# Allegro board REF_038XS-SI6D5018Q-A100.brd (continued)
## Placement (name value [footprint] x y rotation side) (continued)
NOREF#498  -  []  266.97 246.58 0 top
NOREF#499  -  []  236.65 207.92 0 top
NOREF#500  -  []  232.14 182.07 0 top
NOREF#501  -  []  102.38 170.43 0 top
NOREF#502  -  []  227.91 178.48 90 top
NOREF#503  -  []  232.16 241.38 0 top
NOREF#504  -  []  211.64 253.86 90 top
NOREF#505  -  []  252.33 242.3 90 top
NOREF#506  -  []  269.23 240.41 0 top
NOREF#507  -  []  456.55 241.07 0 top
NOREF#508  -  []  292.96 243.2 0 top
NOREF#509  -  []  351.19 209.1 90 top
NOREF#510  -  []  312.45 243.7 90 top
NOREF#511  -  []  308.01 234.3 90 top
NOREF#512  -  []  253.29 182.3 90 top
NOREF#513  -  []  467.84 202.51 0 top
NOREF#514  -  []  318.71 141.78 90 top
NOREF#515  -  []  470.3 249.7 0 top
NOREF#516  -  []  229.86 179.12 90 top
NOREF#517  -  []  221.62 289.14 90 top
NOREF#518  -  []  310.86 245.29 0 top
NOREF#519  -  []  231.16 185.61 0 top
NOREF#520  -  []  215.56 240.9 90 top
NOREF#521  -  []  224.52 282.62 0 top
NOREF#522  -  []  281.34 136.1 0 top
NOREF#523  -  []  116.29 246.5 90 top
NOREF#524  -  []  283.55 213.3 0 top
NOREF#525  -  []  303.71 291.06 0 top
NOREF#526  -  []  286.03 274.19 0 top
NOREF#527  -  []  268.57 245.61 0 top
NOREF#528  -  []  308.57 245.61 0 top
NOREF#529  -  []  304.52 289.22 90 top
NOREF#530  -  []  309.53 238.82 90 top
NOREF#531  -  []  254.68 242.3 90 top
NOREF#532  -  []  228.25 234.12 90 top
NOREF#533  -  []  349.53 238.82 0 top
NOREF#534  -  []  327.07 268.22 90 top
NOREF#535  -  []  322.56 269.73 0 top
NOREF#536  -  []  293.54 250.69 90 top
NOREF#537  -  []  213.09 255.5 0 top
NOREF#538  -  []  211.64 255.18 0 top
NOREF#539  -  []  314.1 283.17 90 top
NOREF#540  -  []  211.33 267.13 0 top
NOREF#541  -  []  253.61 182 90 top
NOREF#542  -  []  316.65 267.92 90 top
NOREF#543  -  []  346.97 245.93 90 top
NOREF#544  -  []  215.16 239.65 90 top
NOREF#545  -  []  102.08 138.36 90 top
NOREF#546  -  []  121.88 172.65 90 top
NOREF#547  -  []  309.59 185.29 90 top
NOREF#548  -  []  552.28 166.69 0 top
NOREF#549  -  []  343.27 288.24 90 top
NOREF#550  -  []  344.09 171.46 90 top
NOREF#551  -  []  107.94 219.95 0 top
NOREF#552  -  []  350.89 242.68 90 top
NOREF#553  -  []  291.34 194.86 0 top
NOREF#554  -  []  112.42 136.82 90 top
NOREF#555  -  []  275.12 295.18 90 top
NOREF#556  -  []  295.01 253.56 90 top
NOREF#557  -  []  333.1 238.82 90 top
NOREF#558  -  []  228.66 166.14 0 top
NOREF#559  -  []  282.91 267.92 0 top
NOREF#560  -  []  229.59 247.23 0 top
NOREF#561  -  []  311.84 244.96 0 top
NOREF#562  -  []  534.23 209.54 0 top
NOREF#563  -  []  350.5 241.72 90 top
NOREF#564  -  []  84.29 158.1 0 top
NOREF#565  -  []  254.36 254.76 0 top
NOREF#566  -  []  273.11 183.7 90 top
NOREF#567  -  []  280.81 218.16 90 top
NOREF#568  -  []  276.23 163.88 90 top
NOREF#569  -  []  236.89 133.69 0 top
NOREF#570  -  []  333.22 251.59 0 top
NOREF#571  -  []  107.94 251.7 0 top
NOREF#572  -  []  369.83 203.63 90 top
NOREF#573  -  []  300.33 189.91 0 top
NOREF#574  -  []  268.44 202.36 0 top
NOREF#575  -  []  219.41 226.69 0 top
NOREF#576  -  []  313.43 189.88 90 top
NOREF#577  -  []  283.55 273.3 0 top
NOREF#578  -  []  349.59 246.58 90 top
NOREF#579  -  []  286.75 209.12 0 top
NOREF#580  -  []  268.57 185.61 0 top
NOREF#581  -  []  241.44 190.47 0 top
NOREF#582  -  []  214.38 183.29 0 top
NOREF#583  -  []  486.4 188.2 0 top
NOREF#584  -  []  269.53 184.02 0 top
NOREF#585  -  []  353.1 183.7 90 top
NOREF#586  -  []  121.88 233.61 90 top
NOREF#587  -  []  318.32 142.99 0 top
NOREF#588  -  []  311.48 245.96 90 top
NOREF#589  -  []  230.73 226.09 0 top
NOREF#590  -  []  360.81 208.22 90 top
NOREF#591  -  []  244.79 211.56 0 top
NOREF#592  -  []  90.79 196.32 0 top
NOREF#593  -  []  478.18 232.07 90 top
NOREF#594  -  []  350.83 243.37 0 top
NOREF#595  -  []  212.13 13.07 0 top
NOREF#596  -  []  263.71 280.78 90 top
NOREF#597  -  []  350.18 178.82 0 top
NOREF#598  -  []  229.89 186.91 0 top
NOREF#599  -  []  335.06 254.76 0 top
NOREF#600  -  []  244.6 208.22 90 top
NOREF#601  -  []  361.13 207.92 90 top
NOREF#602  -  []  267.63 247.88 0 top
NOREF#603  -  []  295.71 193.56 90 top
NOREF#604  -  []  265.88 175.27 0 top
NOREF#605  -  []  358.32 142.99 0 top
NOREF#606  -  []  91.84 249.7 0 top
NOREF#607  -  []  355.48 294.56 0 top
NOREF#608  -  []  253.61 242 90 top
NOREF#609  -  []  48.53 250.3 0 top
NOREF#610  -  []  334.36 194.76 0 top
NOREF#611  -  []  261.62 293.19 90 top
NOREF#612  -  []  308.22 242.08 90 top
NOREF#613  -  []  267.58 184.06 90 top
NOREF#614  -  []  67.34 265.88 90 top
NOREF#615  -  []  355.44 194.76 90 top
NOREF#616  -  []  229.33 210.27 0 top
NOREF#617  -  []  121.88 141.55 0 top
NOREF#618  -  []  112.92 143.87 0 top
NOREF#619  -  []  90.64 253.35 0 top
NOREF#620  -  []  267.77 173.98 0 top
NOREF#621  -  []  291.16 176.15 90 top
NOREF#622  -  []  352.13 178.82 90 top
NOREF#623  -  []  285.58 273.87 90 top
NOREF#624  -  []  276.29 209.25 90 top
NOREF#625  -  []  231.16 241.72 90 top
NOREF#626  -  []  100.39 249.7 0 top
NOREF#627  -  []  332.01 194.76 0 top
NOREF#628  -  []  213.29 242.3 90 top
NOREF#629  -  []  315.48 295.57 0 top
NOREF#630  -  []  348.55 238.48 90 top
NOREF#631  -  []  259.72 293.16 0 top
NOREF#632  -  []  220.67 289.14 0 top
NOREF#633  -  []  324.49 268.86 0 top
NOREF#634  -  []  115.04 249.7 0 top
NOREF#635  -  []  309.5 268.8 0 top
NOREF#636  -  []  310.83 191.08 0 top
NOREF#637  -  []  291.31 254.76 0 top
NOREF#638  -  []  271.16 181.72 90 top
NOREF#639  -  []  535.51 219.75 90 top
NOREF#640  -  []  250.61 240.7 0 top
NOREF#641  -  []  349.59 247.23 0 top
NOREF#642  -  []  312.78 191.08 0 top
NOREF#643  -  []  332.96 183.2 0 top
NOREF#644  -  []  235.48 293.54 0 top
NOREF#645  -  []  235.06 250.18 90 top
NOREF#646  -  []  291.64 253.86 90 top
NOREF#647  -  []  240.37 135.17 90 top
NOREF#648  -  []  270.57 208.63 90 top
NOREF#649  -  []  355.91 163.58 90 top
NOREF#650  -  []  271.84 246.26 0 top
NOREF#651  -  []  331.16 176.15 90 top
NOREF#652  -  []  299.33 256.13 0 top
NOREF#653  -  []  353.17 291.16 0 top
NOREF#654  -  []  483 186.2 0 top
NOREF#655  -  []  468.1 186.2 0 top
NOREF#656  -  []  212.33 242.3 90 top
NOREF#657  -  []  65.15 254.33 90 top
NOREF#658  -  []  315.48 293.54 0 top
NOREF#659  -  []  265.68 185.93 0 top
NOREF#660  -  []  267.58 178.18 90 top
NOREF#661  -  []  292.78 250.69 90 top
NOREF#662  -  []  259.41 226.69 0 top
NOREF#663  -  []  352.13 241.42 90 top
NOREF#664  -  []  339.41 221.54 90 top
NOREF#665  -  []  121.19 221.6 0 top
NOREF#666  -  []  272.14 240.12 0 top
NOREF#667  -  []  461 180.6 0 top
NOREF#668  -  []  84.1 279.05 0 top
NOREF#669  -  []  80.47 279.45 0 top
NOREF#670  -  []  456.64 138.68 90 top
NOREF#671  -  []  347.58 184.06 90 top
NOREF#672  -  []  503.64 224.82 90 top
NOREF#673  -  []  355.12 293.93 0 top
NOREF#674  -  []  90.88 169.16 90 top
NOREF#675  -  []  88.89 219.95 0 top
NOREF#676  -  []  223.71 291.06 0 top
NOREF#677  -  []  312.16 241.38 0 top
NOREF#678  -  []  503.94 225.14 0 top
NOREF#679  -  []  461.75 186.2 0 top
NOREF#680  -  []  283.98 267.75 90 top
NOREF#681  -  []  251.16 251.72 0 top
NOREF#682  -  []  253.22 238.82 90 top
NOREF#683  -  []  310.57 208.63 90 top
NOREF#684  -  []  212.54 183.29 90 top
NOREF#685  -  []  85.49 186.2 0 top
NOREF#686  -  []  217.83 263.63 90 top
NOREF#687  -  []  109.42 197.22 90 top
NOREF#688  -  []  110.89 249.7 0 top
NOREF#689  -  []  291.83 203.63 0 top
NOREF#690  -  []  213.09 243.93 0 top
NOREF#691  -  []  344.52 286.56 90 top
NOREF#692  -  []  211.16 176.15 90 top
NOREF#693  -  []  228.24 178.18 90 top
NOREF#694  -  []  292.01 254.76 0 top
NOREF#695  -  []  353.03 294.95 0 top
NOREF#696  -  []  308.25 174.12 90 top
NOREF#697  -  []  251.96 193.56 90 top
NOREF#698  -  []  270.18 183.37 0 top
NOREF#699  -  []  229.15 270.03 90 top
NOREF#700  -  []  227.05 134.31 0 top
NOREF#701  -  []  253.09 255.5 0 top
NOREF#702  -  []  90.79 145.82 0 top
NOREF#703  -  []  307.9 182.38 90 top
NOREF#704  -  []  351.84 186.26 0 top
NOREF#705  -  []  333.61 182 90 top
NOREF#706  -  []  247.56 272.93 0 top
NOREF#707  -  []  350.91 187.88 0 top
NOREF#708  -  []  558.12 150.18 0 top
NOREF#709  -  []  273.99 268.8 90 top
NOREF#710  -  []  301.29 292.89 0 top
NOREF#711  -  []  236.7 293.15 90 top
NOREF#712  -  []  347.77 234.98 0 top
NOREF#713  -  []  274.82 281.03 0 top
NOREF#714  -  []  95.79 158.1 0 top
NOREF#715  -  []  220.66 166.14 0 top
NOREF#716  -  []  365.29 272.67 0 top
NOREF#717  -  []  235.21 281.4 90 top
NOREF#718  -  []  263.27 175.18 0 top
NOREF#719  -  []  253.39 195.18 0 top
NOREF#720  -  []  466.15 249.7 0 top
NOREF#721  -  []  472.5 217.95 0 top
NOREF#722  -  []  265.68 245.93 0 top
NOREF#723  -  []  347.64 180.73 90 top
NOREF#724  -  []  347.94 181.06 0 top
NOREF#725  -  []  308.26 222.94 90 top
NOREF#726  -  []  540.55 206.94 90 top
NOREF#727  -  []  95.24 212.35 0 top
NOREF#728  -  []  295.06 194.76 0 top
NOREF#729  -  []  355.91 223.58 90 top
NOREF#730  -  []  263.71 285.73 0 top
NOREF#731  -  []  270.19 238.82 0 top
NOREF#732  -  []  456.55 132.82 90 top
NOREF#733  -  []  255.38 242.3 90 top
NOREF#734  -  []  269.53 178.82 90 top
NOREF#735  -  []  347.63 247.23 90 top
NOREF#736  -  []  310.84 238.82 0 top
NOREF#737  -  []  211.83 170.23 315 top
NOREF#738  -  []  83.8 279.38 0 top
NOREF#739  -  []  314.61 295.18 90 top
NOREF#740  -  []  263.95 233.82 90 top
NOREF#741  -  []  265.48 175.27 0 top
NOREF#742  -  []  120.64 244.1 0 top
NOREF#743  -  []  254.68 255.18 0 top
NOREF#744  -  []  295.58 254.86 90 top
NOREF#745  -  []  271.16 239.12 90 top
NOREF#746  -  []  467.84 170.76 0 top
NOREF#747  -  []  267.27 246.26 0 top
NOREF#748  -  []  284.35 211.05 90 top
NOREF#749  -  []  267.25 174.3 90 top
NOREF#750  -  []  95.24 219.95 0 top
NOREF#751  -  []  252.54 194.86 90 top
NOREF#752  -  []  315.23 163.88 90 top
NOREF#753  -  []  367.88 212.03 90 top
NOREF#754  -  []  212.33 182.3 90 top
NOREF#755  -  []  305.44 146.16 90 top
NOREF#756  -  []  474.45 186.2 0 top
NOREF#757  -  []  102.34 186.2 0 top
NOREF#758  -  []  267.64 181.38 90 top
NOREF#759  -  []  312.16 181.38 0 top
NOREF#760  -  []  346.28 251.08 0 top
NOREF#761  -  []  357.95 140.86 90 top
NOREF#762  -  []  223.27 235.18 0 top
NOREF#763  -  []  291.96 193.56 90 top
NOREF#764  -  []  247.88 272.03 90 top
NOREF#765  -  []  101.59 188.2 0 top
NOREF#766  -  []  229.53 184.02 90 top
NOREF#767  -  []  244.05 272.03 90 top
NOREF#768  -  []  278.39 139.82 90 top
NOREF#769  -  []  348.27 244.64 90 top
NOREF#770  -  []  264.42 175.77 0 top
NOREF#771  -  []  271.21 187.56 0 top
NOREF#772  -  []  266.61 239.75 90 top
NOREF#773  -  []  307.27 246.26 0 top
NOREF#774  -  []  347.58 178.18 90 top
NOREF#775  -  []  231.44 240.08 90 top
NOREF#776  -  []  482.05 151.25 90 top
NOREF#777  -  []  307.94 181.7 0 top
NOREF#778  -  []  272.74 184.64 90 top
NOREF#779  -  []  344.91 233.9 0 top
NOREF#780  -  []  456 275.24 90 top
NOREF#781  -  []  467.84 236.8 0 top
NOREF#782  -  []  116.04 189.85 0 top
NOREF#783  -  []  546.96 198.04 0 top
NOREF#784  -  []  271.81 241.72 90 top
NOREF#785  -  []  325.29 272.67 0 top
NOREF#786  -  []  229.53 178.82 0 top
NOREF#787  -  []  251.83 230.23 315 top
NOREF#788  -  []  275.12 294.17 90 top
NOREF#789  -  []  251.16 236.15 90 top
NOREF#790  -  []  350.83 184.63 90 top
NOREF#791  -  []  227.59 184.06 0 top
NOREF#792  -  []  212.54 243.29 90 top
NOREF#793  -  []  233.76 243.65 0 top
NOREF#794  -  []  104.54 217.95 0 top
NOREF#795  -  []  310.54 184.96 0 top
NOREF#796  -  []  349.85 179.12 90 top
NOREF#797  -  []  33.01 2.28 90 top
NOREF#798  -  []  230.84 187.16 0 top
NOREF#799  -  []  307.64 241.37 0 top
NOREF#800  -  []  83.8 262.11 90 top
NOREF#801  -  []  354.65 243.33 90 top
NOREF#802  -  []  350.57 208.63 0 top
NOREF#803  -  []  263.09 233.82 0 top
NOREF#804  -  []  310.51 179.12 90 top
NOREF#805  -  []  332.33 182.3 90 top
NOREF#806  -  []  247.4 207.92 90 top
NOREF#807  -  []  260.66 226.14 0 top
NOREF#808  -  []  122.18 141.22 0 top
NOREF#809  -  []  251.64 195.18 0 top
NOREF#810  -  []  462.75 189.85 0 top
NOREF#811  -  []  121.88 201.86 90 top
NOREF#812  -  []  120.64 251.7 0 top
NOREF#813  -  []  240.81 158.16 0 top
NOREF#814  -  []  552.28 150.18 0 top
NOREF#815  -  []  212.78 250.69 90 top
NOREF#816  -  []  234.78 182.68 0 top
NOREF#817  -  []  303.34 286.27 90 top
NOREF#818  -  []  333.09 243.29 90 top
NOREF#819  -  []  294.36 193.12 0 top
NOREF#820  -  []  305.43 292.08 90 top
NOREF#821  -  []  254.36 193.12 0 top
NOREF#822  -  []  480.8 217.95 0 top
NOREF#823  -  []  224.52 285.16 0 top
NOREF#824  -  []  272.46 242.37 90 top
NOREF#825  -  []  225.96 248.85 90 top
NOREF#826  -  []  323.98 207.75 0 top
NOREF#827  -  []  347.75 235.77 0 top
NOREF#828  -  []  549.91 154.6 0 top
NOREF#829  -  []  259.41 166.69 0 top
NOREF#830  -  []  307.58 178.18 0 top
NOREF#831  -  []  265.33 134.7 0 top
NOREF#832  -  []  238.39 139.82 90 top
NOREF#833  -  []  317.95 146.07 90 top
NOREF#834  -  []  102.08 141.55 0 top
NOREF#835  -  []  325.9 272.03 0 top
NOREF#836  -  []  349.89 186.91 0 top
NOREF#837  -  []  319.44 136.62 90 top
NOREF#838  -  []  263.71 283.32 90 top
NOREF#839  -  []  363.37 213.06 90 top
NOREF#840  -  []  266.91 144.24 90 top
NOREF#841  -  []  252.33 253.86 90 top
NOREF#842  -  []  109.94 183 90 top
NOREF#843  -  []  303.95 174.94 90 top
NOREF#844  -  []  306.97 246.58 0 top
NOREF#845  -  []  227.77 234.98 0 top
NOREF#846  -  []  120.64 148.85 0 top
NOREF#847  -  []  37.49 250.69 0 top
NOREF#848  -  []  228.93 181.38 0 top
NOREF#849  -  []  353.4 294.56 0 top
NOREF#850  -  []  364.05 272.03 90 top
NOREF#851  -  []  456.55 132.82 0 top
NOREF#852  -  []  214.68 193.86 90 top
NOREF#853  -  []  364.49 268.86 0 top
NOREF#854  -  []  315.91 223.58 90 top
NOREF#855  -  []  310.89 243.32 0 top
NOREF#856  -  []  66.31 248.1 0 top
NOREF#857  -  []  251.31 194.76 0 top
NOREF#858  -  []  272.46 250.18 90 top
NOREF#859  -  []  213.29 182.3 90 top
NOREF#860  -  []  347.9 244.36 90 top
NOREF#861  -  []  463.95 154.45 0 top
NOREF#862  -  []  318.22 208.86 0 top
NOREF#863  -  []  270.19 178.82 0 top
NOREF#864  -  []  116.29 151.25 90 top
NOREF#865  -  []  351.15 250.18 90 top
NOREF#866  -  []  455.2 158.1 0 top
NOREF#867  -  []  475.7 214.75 90 top
NOREF#868  -  []  285.1 208.22 0 top
NOREF#869  -  []  350.91 247.88 0 top
NOREF#870  -  []  345.88 235.27 0 top
NOREF#871  -  []  233.99 268.8 90 top
NOREF#872  -  []  310.18 243.37 90 top
NOREF#873  -  []  101.59 148.85 0 top
NOREF#874  -  []  282.64 267.56 0 top
NOREF#875  -  []  120.02 227.57 90 top
NOREF#876  -  []  250.61 247.17 90 top
NOREF#877  -  []  0 0 90 top
NOREF#878  -  []  539.84 233.33 0 top
NOREF#879  -  []  469.35 246.5 90 top
NOREF#880  -  []  241.13 267.92 90 top
NOREF#881  -  []  311.54 245.93 90 top
NOREF#882  -  []  312.13 241.42 90 top
NOREF#883  -  []  273.34 270 0 top
NOREF#884  -  []  232.13 249.88 90 top
NOREF#885  -  []  285.73 214.51 0 top
NOREF#886  -  []  242.74 209.49 0 top
NOREF#887  -  []  313.17 291.16 0 top
NOREF#888  -  []  461 156.45 0 top
NOREF#889  -  []  306.93 178.18 90 top
NOREF#890  -  []  498.63 206.03 0 top
NOREF#891  -  []  295.71 182 90 top
NOREF#892  -  []  468.1 217.95 0 top
NOREF#893  -  []  85.49 154.45 0 top
NOREF#894  -  []  222.22 288.34 90 top
NOREF#895  -  []  455.67 276.14 0 top
NOREF#896  -  []  229.23 208.44 0 top
NOREF#897  -  []  331.33 267.13 0 top
NOREF#898  -  []  114.84 253.35 0 top
NOREF#899  -  []  327.88 272.03 90 top
NOREF#900  -  []  231.54 184.64 0 top
NOREF#901  -  []  354.44 146.64 0 top
NOREF#902  -  []  227.26 178.48 90 top
NOREF#903  -  []  363.72 211.73 0 top
NOREF#904  -  []  120.64 219.95 0 top
NOREF#905  -  []  243.98 207.75 0 top
NOREF#906  -  []  254.36 181.55 0 top
NOREF#907  -  []  503.5 205.13 90 top
NOREF#908  -  []  310.18 242.62 0 top
NOREF#909  -  []  318.33 208.22 90 top
NOREF#910  -  []  293.39 255.18 0 top
NOREF#911  -  []  112.92 175.62 0 top
NOREF#912  -  []  290.56 252.32 0 top
NOREF#913  -  []  225.68 245.93 0 top
NOREF#914  -  []  210.61 175.6 90 top
NOREF#915  -  []  81.36 261.94 0 top
NOREF#916  -  []  109.42 228.97 90 top
NOREF#917  -  []  353.45 243.33 0 top
NOREF#918  -  []  246.75 269.12 0 top
NOREF#919  -  []  299.41 161.54 90 top
NOREF#920  -  []  264.41 231.76 90 top
NOREF#921  -  []  274.91 223.58 0 top
NOREF#922  -  []  112.92 239.12 0 top
NOREF#923  -  []  108.69 186.2 0 top
NOREF#924  -  []  318.83 208.22 0 top
NOREF#925  -  []  541.95 210.34 90 top
NOREF#926  -  []  278.33 208.22 90 top
NOREF#927  -  []  349.53 178.82 0 top
NOREF#928  -  []  351.48 242.62 0 top
NOREF#929  -  []  344.41 171.76 90 top
NOREF#930  -  []  503.64 225.47 0 top
NOREF#931  -  []  280.81 268.22 90 top
NOREF#932  -  []  547.04 236.7 90 top
NOREF#933  -  []  232.23 227.99 90 top
NOREF#934  -  []  287.88 272.03 90 top
NOREF#935  -  []  232.79 243.4 90 top
NOREF#936  -  []  229.15 210.03 90 top
NOREF#937  -  []  294.38 194.86 0 top
NOREF#938  -  []  309.15 210.51 0 top
NOREF#939  -  []  305.95 188.86 0 top
NOREF#940  -  []  346.97 186.58 0 top
NOREF#941  -  []  231.81 179.12 90 top
NOREF#942  -  []  215.01 253.56 90 top
NOREF#943  -  []  255.06 254.76 0 top
NOREF#944  -  []  231.48 189.88 90 top
NOREF#945  -  []  103.59 214.75 90 top
NOREF#946  -  []  236.37 207.56 0 top
NOREF#947  -  []  269.23 181.06 0 top
NOREF#948  -  []  275.08 183 0 top
NOREF#949  -  []  235.91 223.58 0 top
NOREF#950  -  []  210.56 192.32 0 top
NOREF#951  -  []  253.1 190.39 90 top
NOREF#952  -  []  267.05 134.31 90 top
NOREF#953  -  []  286.24 298.16 0 top
NOREF#954  -  []  267.9 178.48 90 top
NOREF#955  -  []  307.75 235.77 0 top
NOREF#956  -  []  308.01 174.3 90 top
NOREF#957  -  []  346.93 238.18 0 top
NOREF#958  -  []  122.64 183 90 top
NOREF#959  -  []  270.24 180.08 0 top
NOREF#960  -  []  227.91 182.38 90 top
NOREF#961  -  []  352.78 243.4 90 top
NOREF#962  -  []  231.48 251.08 0 top
NOREF#963  -  []  343.71 288.4 0 top
NOREF#964  -  []  227.59 238.18 0 top
NOREF#965  -  []  233.11 183.7 90 top
NOREF#966  -  []  343.71 285.98 90 top
NOREF#967  -  []  348.93 240.73 0 top
NOREF#968  -  []  324.35 271.05 90 top
NOREF#969  -  []  475.7 183 90 top
NOREF#970  -  []  293.22 190.39 90 top
NOREF#971  -  []  324.79 271.56 90 top
NOREF#972  -  []  271.81 179.12 90 top
NOREF#973  -  []  349.85 239.12 90 top
NOREF#974  -  []  303.27 288.24 90 top
NOREF#975  -  []  334.31 182 90 top
NOREF#976  -  []  223.71 283.19 0 top
NOREF#977  -  []  354.44 138.77 0 top
NOREF#978  -  []  106.74 249.7 0 top
NOREF#979  -  []  454.65 244.1 0 top
NOREF#980  -  []  352.12 249.88 90 top
NOREF#981  -  []  214.38 194.86 0 top
NOREF#982  -  []  302.86 226.14 0 top
NOREF#983  -  []  275.48 294.56 0 top
NOREF#984  -  []  542.34 223.67 90 top
NOREF#985  -  []  268.23 242.08 90 top
NOREF#986  -  []  268.55 238.48 90 top
NOREF#987  -  []  110.89 186.2 0 top
NOREF#988  -  []  303.95 234.38 90 top
NOREF#989  -  []  223.71 285.73 0 top
NOREF#990  -  []  425.01 290.38 90 top
NOREF#991  -  []  483 249.7 0 top
NOREF#992  -  []  351.15 185.61 0 top
NOREF#993  -  []  243.72 271.73 90 top
NOREF#994  -  []  327.65 160.09 90 top
NOREF#995  -  []  276.37 267.56 0 top
NOREF#996  -  []  217.83 271.13 0 top
NOREF#997  -  []  223.09 232.9 0 top
NOREF#998  -  []  488.4 214.75 90 top
NOREF#999  -  []  359.72 136.37 0 top
NOREF#1000  -  []  347.27 246.26 0 top
NOREF#1001  -  []  482.51 133.82 90 top
NOREF#1002  -  []  467.35 188.2 0 top
NOREF#1003  -  []  273.43 249.88 90 top
NOREF#1004  -  []  558.12 147.98 0 top
NOREF#1005  -  []  240.48 269.12 0 top
NOREF#1006  -  []  482.51 197.32 90 top
NOREF#1007  -  []  353.63 146.07 0 top
NOREF#1008  -  []  232.46 181.7 0 top
NOREF#1009  -  []  109.42 133.72 90 top
NOREF#1010  -  []  230.91 187.88 0 top
NOREF#1011  -  []  306.93 178.18 0 top
NOREF#1012  -  []  293.54 239.12 90 top
NOREF#1013  -  []  273.66 209.1 90 top
NOREF#1014  -  []  329.83 203.63 90 top
NOREF#1015  -  []  349.15 270.03 90 top
NOREF#1016  -  []  0 429.26 0 top
NOREF#1017  -  []  295.73 296 90 top
NOREF#1018  -  []  229.25 134 0 top
NOREF#1019  -  []  278.71 141.78 90 top
NOREF#1020  -  []  102.14 221.6 0 top
NOREF#1021  -  []  350.89 183.33 0 top
NOREF#1022  -  []  231.19 269.1 90 top
NOREF#1023  -  []  344.42 175.77 0 top
NOREF#1024  -  []  313.63 146.07 0 top
NOREF#1025  -  []  353.75 183.65 0 top
NOREF#1026  -  []  309.59 245.93 90 top
NOREF#1027  -  []  255.56 180.9 90 top
NOREF#1028  -  []  348.25 174.12 90 top
NOREF#1029  -  []  265.68 185.29 90 top
NOREF#1030  -  []  267.75 235.77 0 top
NOREF#1031  -  []  234.66 183.33 90 top
NOREF#1032  -  []  252.45 250.39 0 top
NOREF#1033  -  []  487.64 236.15 90 top
NOREF#1034  -  []  271.16 179.12 90 top
NOREF#1035  -  []  291.83 230.23 315 top
NOREF#1036  -  []  351.15 245.61 0 top
NOREF#1037  -  []  320.81 218.66 90 top
NOREF#1038  -  []  343.09 173.82 0 top
NOREF#1039  -  []  303.71 283.32 90 top
NOREF#1040  -  []  323.83 218.13 90 top
NOREF#1041  -  []  310.24 184.64 90 top
NOREF#1042  -  []  321.44 250.47 0 top
NOREF#1043  -  []  102.38 141.22 0 top
NOREF#1044  -  []  223.56 295.96 0 top
NOREF#1045  -  []  311.16 186.26 90 top
NOREF#1046  -  []  278.33 268.22 90 top
NOREF#1047  -  []  454.65 188.2 0 top
NOREF#1048  -  []  334.38 243.29 0 top
NOREF#1049  -  []  230.5 183.67 90 top
NOREF#1050  -  []  230.55 134.62 90 top
NOREF#1051  -  []  470.3 154.45 0 top
NOREF#1052  -  []  311.54 184.64 0 top
NOREF#1053  -  []  245.29 212.67 0 top
NOREF#1054  -  []  246.03 274.19 0 top
NOREF#1055  -  []  227.64 181.38 0 top
NOREF#1056  -  []  230.18 182.62 0 top
NOREF#1057  -  []  48.16 249.91 0 top
NOREF#1058  -  []  322.57 160.09 0 top
NOREF#1059  -  []  322.56 209.25 90 top
NOREF#1060  -  []  292.66 253.56 90 top
NOREF#1061  -  []  272.46 190.18 90 top
NOREF#1062  -  []  310.57 268.63 0 top
NOREF#1063  -  []  267.58 244.06 90 top
NOREF#1064  -  []  362.33 233.13 90 top
NOREF#1065  -  []  271.49 240.02 0 top
NOREF#1066  -  []  315.08 183 0 top
NOREF#1067  -  []  539.84 220.37 0 top
NOREF#1068  -  []  313.63 140.86 0 top
NOREF#1069  -  []  232.14 242.07 90 top
NOREF#1070  -  []  322.91 267.92 90 top
NOREF#1071  -  []  228.93 180.09 90 top
NOREF#1072  -  []  130.05 260.06 90 top
NOREF#1073  -  []  95.24 180.6 0 top
NOREF#1074  -  []  211.83 230.23 315 top
NOREF#1075  -  []  224.09 171.46 90 top
NOREF#1076  -  []  238.83 268.22 0 top
NOREF#1077  -  []  342.95 288.54 90 top
NOREF#1078  -  []  266.54 134.31 90 top
NOREF#1079  -  []  277.14 141.43 90 top
NOREF#1080  -  []  228.49 136.9 90 top
NOREF#1081  -  []  354.61 294.17 90 top
NOREF#1082  -  []  311.69 209.1 0 top
NOREF#1083  -  []  335.56 180.9 90 top
NOREF#1084  -  []  317.14 141.43 90 top
NOREF#1085  -  []  262.96 165.63 90 top
NOREF#1086  -  []  546.66 211.81 90 top
NOREF#1087  -  []  268.93 180.74 90 top
NOREF#1088  -  []  347.05 133.3 90 top
NOREF#1089  -  []  335.56 252.47 90 top
NOREF#1090  -  []  350.18 178.82 90 top
NOREF#1091  -  []  242.33 233.13 90 top
NOREF#1092  -  []  272.12 249.88 90 top
NOREF#1093  -  []  302.95 288.54 90 top
NOREF#1094  -  []  269.59 186.59 90 top
NOREF#1095  -  []  333.1 250.39 90 top
NOREF#1096  -  []  353.45 183.33 0 top
NOREF#1097  -  []  280.81 158.66 90 top
NOREF#1098  -  []  543.62 171.5 0 top
NOREF#1099  -  []  540.03 233.63 0 top
NOREF#1100  -  []  263.95 234.38 90 top
NOREF#1101  -  []  348.57 185.61 0 top
NOREF#1102  -  []  478.85 186.2 0 top
NOREF#1103  -  []  308.27 185.29 90 top
NOREF#1104  -  []  252.66 242 90 top
NOREF#1105  -  []  229.53 238.82 0 top
NOREF#1106  -  []  226.94 178.18 90 top
NOREF#1107  -  []  241.13 207.92 90 top
NOREF#1108  -  []  211.83 203.63 0 top
NOREF#1109  -  []  461.07 197.47 90 top
NOREF#1110  -  []  323.24 208.22 90 top
NOREF#1111  -  []  310.54 244.96 0 top
NOREF#1112  -  []  349.46 145.44 90 top
NOREF#1113  -  []  90.88 170.43 90 top
NOREF#1114  -  []  355.23 163.88 90 top
NOREF#1115  -  []  90.79 145.82 0 top
NOREF#1116  -  []  469.1 189.85 0 top
NOREF#1117  -  []  306.93 238.18 90 top
NOREF#1118  -  []  315.05 190.18 90 top
NOREF#1119  -  []  211.64 182.3 90 top
NOREF#1120  -  []  250.56 247.12 90 top
NOREF#1121  -  []  312.46 180.42 90 top
NOREF#1122  -  []  323.37 273.54 0 top
NOREF#1123  -  []  315.91 223.58 0 top
NOREF#1124  -  []  83.2 262.88 90 top
NOREF#1125  -  []  352.13 183.41 90 top
NOREF#1126  -  []  348.27 185.28 0 top
NOREF#1127  -  []  294.36 194.76 0 top
NOREF#1128  -  []  369.83 263.63 90 top
NOREF#1129  -  []  227.64 242.02 0 top
NOREF#1130  -  []  235.12 295.18 90 top
NOREF#1131  -  []  461.55 221.6 0 top
NOREF#1132  -  []  309.53 244.02 90 top
NOREF#1133  -  []  356.97 268.22 90 top
NOREF#1134  -  []  272.46 241.7 0 top
NOREF#1135  -  []  320.81 268.22 90 top
NOREF#1136  -  []  313.46 183.33 0 top
NOREF#1137  -  []  265.48 173.73 90 top
NOREF#1138  -  []  230.83 181.42 90 top
NOREF#1139  -  []  308.93 208.11 0 top
NOREF#1140  -  []  265.48 233.73 90 top
NOREF#1141  -  []  275.44 254.76 90 top
NOREF#1142  -  []  473.7 219.95 0 top
NOREF#1143  -  []  553.49 166.3 90 top
NOREF#1144  -  []  364.6 268.22 90 top
NOREF#1145  -  []  271.47 249.88 90 top
NOREF#1146  -  []  360.81 158.66 90 top
NOREF#1147  -  []  316.29 209.73 0 top
NOREF#1148  -  []  468.14 233.93 0 top
NOREF#1149  -  []  293.99 253.86 90 top
NOREF#1150  -  []  312.23 227.99 0 top
NOREF#1151  -  []  335.83 199.63 0 top
NOREF#1152  -  []  262.22 288.34 90 top
NOREF#1153  -  []  227.94 241.7 0 top
NOREF#1154  -  []  310.24 244.64 90 top
NOREF#1155  -  []  352.45 241.7 0 top
NOREF#1156  -  []  367.56 272.93 0 top
NOREF#1157  -  []  83.8 290.99 90 top
NOREF#1158  -  []  309.5 268.8 90 top
NOREF#1159  -  []  474.45 154.45 0 top
NOREF#1160  -  []  266.93 238.18 0 top
NOREF#1161  -  []  322.64 207.56 0 top
NOREF#1162  -  []  238.71 141.78 90 top
NOREF#1163  -  []  243.72 211.73 0 top
NOREF#1164  -  []  456.55 228.07 90 top
NOREF#1165  -  []  102.08 202.51 0 top
NOREF#1166  -  []  503.03 205.98 90 top
NOREF#1167  -  []  362.57 160.09 0 top
NOREF#1168  -  []  349.23 241.06 0 top
NOREF#1169  -  []  315.91 163.58 0 top
NOREF#1170  -  []  253.99 242.3 90 top
NOREF#1171  -  []  291.16 251.72 0 top
NOREF#1172  -  []  293.09 254.86 90 top
NOREF#1173  -  []  534.23 205.35 0 top
NOREF#1174  -  []  267.25 238.48 90 top
NOREF#1175  -  []  352.13 243.4 90 top
NOREF#1176  -  []  467.84 234.26 0 top
NOREF#1177  -  []  351.15 190.18 90 top
NOREF#1178  -  []  308.27 245.29 90 top
NOREF#1179  -  []  312.12 189.88 90 top
NOREF#1180  -  []  212.96 194.76 0 top
NOREF#1181  -  []  539.45 192.64 90 top
NOREF#1182  -  []  280.48 269.12 0 top
NOREF#1183  -  []  345.98 245.61 0 top
NOREF#1184  -  []  89.64 249.7 0 top
NOREF#1185  -  []  102.08 140.9 90 top
NOREF#1186  -  []  247.07 268.22 90 top
NOREF#1187  -  []  219.41 161.54 90 top
NOREF#1188  -  []  351.8 241.72 90 top
NOREF#1189  -  []  120.64 188.2 0 top
NOREF#1190  -  []  250.33 162.13 90 top
NOREF#1191  -  []  98.19 154.45 0 top
NOREF#1192  -  []  348.93 240.09 90 top
NOREF#1193  -  []  269.85 244.32 90 top
NOREF#1194  -  []  263.95 232.9 90 top
NOREF#1195  -  []  456.64 169.16 90 top
NOREF#1196  -  []  310.91 247.23 90 top
NOREF#1197  -  []  487.64 202.51 0 top
NOREF#1198  -  []  534.61 235.83 0 top
NOREF#1199  -  []  304.41 171.76 90 top
NOREF#1200  -  []  269.15 270.51 0 top
NOREF#1201  -  []  333.09 243.93 0 top
NOREF#1202  -  []  223.27 174.06 0 top
NOREF#1203  -  []  315.08 243 0 top
NOREF#1204  -  []  227.59 243.28 0 top
NOREF#1205  -  []  272.79 251.08 0 top
NOREF#1206  -  []  348.93 241.38 0 top
NOREF#1207  -  []  546.96 207.94 0 top
NOREF#1208  -  []  225.88 175.27 0 top
NOREF#1209  -  []  282.24 135.78 90 top
NOREF#1210  -  []  271.16 241.72 90 top
NOREF#1211  -  []  349.59 185.29 90 top
NOREF#1212  -  []  285.9 212.03 0 top
NOREF#1213  -  []  345.43 295.26 0 top
NOREF#1214  -  []  475.18 197.22 90 top
NOREF#1215  -  []  453.45 217.95 0 top
NOREF#1216  -  []  225.06 166.14 0 top
NOREF#1217  -  []  95.24 156.45 0 top
NOREF#1218  -  []  213.09 195.5 0 top
NOREF#1219  -  []  102.34 217.95 0 top
NOREF#1220  -  []  215.58 183.29 90 top
NOREF#1221  -  []  358.22 268.86 0 top
NOREF#1222  -  []  104.54 186.2 0 top
NOREF#1223  -  []  109.94 151.25 90 top
NOREF#1224  -  []  322.74 269.49 0 top
NOREF#1225  -  []  233.11 250.18 90 top
NOREF#1226  -  []  535.13 207.81 90 top
NOREF#1227  -  []  350.18 238.82 0 top
NOREF#1228  -  []  215.01 242 90 top
NOREF#1229  -  []  331.16 180.15 0 top
NOREF#1230  -  []  230.5 250.18 90 top
NOREF#1231  -  []  310.18 243.37 0 top
NOREF#1232  -  []  227.41 134.7 0 top
NOREF#1233  -  []  120.64 212.35 0 top
NOREF#1234  -  []  475.45 253.35 0 top
NOREF#1235  -  []  255.16 239.65 90 top
NOREF#1236  -  []  228.25 173.12 90 top
NOREF#1237  -  []  224.52 287.83 0 top
NOREF#1238  -  []  273.03 295.96 0 top
NOREF#1239  -  []  37.49 247.71 90 top
NOREF#1240  -  []  540.94 233.23 90 top
NOREF#1241  -  []  480.05 180.6 0 top
NOREF#1242  -  []  223.09 172.9 0 top
NOREF#1243  -  []  311.47 189.88 90 top
NOREF#1244  -  []  311.81 179.12 90 top
NOREF#1245  -  []  311.15 250.18 90 top
NOREF#1246  -  []  501.19 205.04 0 top
NOREF#1247  -  []  263.27 234.06 0 top
NOREF#1248  -  []  303.09 233.82 0 top
NOREF#1249  -  []  215.71 182 90 top
NOREF#1250  -  []  95.79 189.85 0 top
NOREF#1251  -  []  482.05 214.75 90 top
NOREF#1252  -  []  120.02 195.82 90 top
NOREF#1253  -  []  326.03 214.19 0 top
NOREF#1254  -  []  114.29 212.35 0 top
NOREF#1255  -  []  276.65 207.92 90 top
NOREF#1256  -  []  225.96 248.85 0 top
NOREF#1257  -  []  482.05 183 90 top
NOREF#1258  -  []  306.97 245.93 90 top
NOREF#1259  -  []  293.09 183.93 0 top
NOREF#1260  -  []  230.89 242.68 90 top
NOREF#1261  -  []  456.4 158.1 0 top
NOREF#1262  -  []  226.06 146.65 90 top
NOREF#1263  -  []  349.53 178.82 90 top
NOREF#1264  -  []  468.14 141.22 0 top
NOREF#1265  -  []  94.04 186.2 0 top
NOREF#1266  -  []  270.91 187.88 0 top
NOREF#1267  -  []  114.29 244.1 0 top
NOREF#1268  -  []  347.85 138.1 0 top
NOREF#1269  -  []  242.64 207.56 0 top
NOREF#1270  -  []  117.42 160.47 90 top
NOREF#1271  -  []  261.29 292.89 0 top
NOREF#1272  -  []  332.54 243.29 90 top
NOREF#1273  -  []  244.05 212.03 90 top
NOREF#1274  -  []  363.55 273.3 0 top
NOREF#1275  -  []  307.77 234.98 0 top
NOREF#1276  -  []  344.96 135.33 90 top
NOREF#1277  -  []  219.41 166.69 0 top
NOREF#1278  -  []  267.56 144.79 90 top
NOREF#1279  -  []  269.59 187.23 0 top
NOREF#1280  -  []  295.56 192.47 90 top
NOREF#1281  -  []  323.72 211.73 90 top
NOREF#1282  -  []  369.83 263.63 90 top
NOREF#1283  -  []  263.56 295.96 0 top
NOREF#1284  -  []  116.75 197.32 90 top
NOREF#1285  -  []  236.23 223.88 90 top
NOREF#1286  -  []  214.31 253.56 90 top
NOREF#1287  -  []  250.56 252.32 0 top
NOREF#1288  -  []  242.34 207.24 0 top
NOREF#1289  -  []  231.44 180.08 90 top
NOREF#1290  -  []  459.07 130.61 0 top
NOREF#1291  -  []  290.61 252.27 0 top
NOREF#1292  -  []  560.49 154.6 0 top
NOREF#1293  -  []  253.99 253.86 90 top
NOREF#1294  -  []  226.94 178.18 0 top
NOREF#1295  -  []  331.31 194.76 0 top
NOREF#1296  -  []  228.25 233.12 90 top
NOREF#1297  -  []  272.14 182.07 90 top
NOREF#1298  -  []  240.81 268.22 90 top
NOREF#1299  -  []  355.12 295.18 0 top
NOREF#1300  -  []  228.27 244.64 90 top
NOREF#1301  -  []  456.55 209.32 0 top
NOREF#1302  -  []  352.13 242.07 90 top
NOREF#1303  -  []  357.14 144.1 90 top
NOREF#1304  -  []  111.42 160.47 0 top
NOREF#1305  -  []  312.23 167.99 90 top
NOREF#1306  -  []  356.52 133.3 0 top
NOREF#1307  -  []  230.5 190.18 90 top
NOREF#1308  -  []  311.84 184.96 0 top
NOREF#1309  -  []  312.13 183.41 90 top
NOREF#1310  -  []  268.23 182.08 90 top
NOREF#1311  -  []  363.54 267.24 90 top
NOREF#1312  -  []  332.96 243.2 0 top
NOREF#1313  -  []  290.33 222.13 90 top
NOREF#1314  -  []  107.94 212.35 0 top
NOREF#1315  -  []  233.03 295.96 0 top
NOREF#1316  -  []  95.24 244.1 0 top
NOREF#1317  -  []  231.15 190.18 90 top
NOREF#1318  -  []  344.52 282.62 0 top
NOREF#1319  -  []  234.75 282.62 90 top
NOREF#1320  -  []  295.38 242.3 90 top
NOREF#1321  -  []  453.45 154.45 0 top
NOREF#1322  -  []  304.09 171.46 0 top
NOREF#1323  -  []  540.03 233.63 90 top
NOREF#1324  -  []  323.72 271.73 90 top
NOREF#1325  -  []  267.58 184.06 0 top
NOREF#1326  -  []  351.21 247.56 0 top
NOREF#1327  -  []  212.54 254.86 90 top
NOREF#1328  -  []  215.56 252.47 90 top
NOREF#1329  -  []  109.42 165.47 90 top
NOREF#1330  -  []  283.72 271.73 0 top
NOREF#1331  -  []  499.83 225.44 90 top
NOREF#1332  -  []  311.19 209.1 90 top
NOREF#1333  -  []  294.38 243.29 0 top
NOREF#1334  -  []  540.94 220.27 90 top
NOREF#1335  -  []  315.83 283.46 0 top
NOREF#1336  -  []  347.56 144.79 0 top
NOREF#1337  -  []  332.33 253.86 90 top
NOREF#1338  -  []  369.83 203.63 90 top
NOREF#1339  -  []  486.4 244.1 0 top
NOREF#1340  -  []  239.44 136.62 90 top
NOREF#1341  -  []  355.48 295.57 0 top
NOREF#1342  -  []  225.14 295.18 90 top
NOREF#1343  -  []  356.65 267.92 90 top
NOREF#1344  -  []  272.13 178.82 90 top
NOREF#1345  -  []  307.9 242.38 90 top
NOREF#1346  -  []  240.81 158.66 90 top
NOREF#1347  -  []  339.33 256.13 0 top
NOREF#1348  -  []  278.83 208.22 0 top
NOREF#1349  -  []  214.31 242 90 top
NOREF#1350  -  []  231.11 292.69 90 top
NOREF#1351  -  []  299.41 221.54 90 top
NOREF#1352  -  []  557.76 147.59 90 top
NOREF#1353  -  []  347.64 241.37 0 top
NOREF#1354  -  []  352.13 251.08 0 top
NOREF#1355  -  []  228.27 245.28 0 top
NOREF#1356  -  []  251.31 243.2 0 top
NOREF#1357  -  []  251.34 183.29 0 top
NOREF#1358  -  []  268.27 245.29 90 top
NOREF#1359  -  []  224.91 173.9 0 top
NOREF#1360  -  []  253.54 190.69 90 top
NOREF#1361  -  []  268.23 178.18 90 top
NOREF#1362  -  []  89.64 217.95 0 top
NOREF#1363  -  []  325.58 213.87 90 top
NOREF#1364  -  []  309.89 246.91 0 top
NOREF#1365  -  []  238.22 268.86 0 top
NOREF#1366  -  []  235.48 294.56 0 top
NOREF#1367  -  []  339.87 267.91 0 top
NOREF#1368  -  []  268.23 178.18 0 top
NOREF#1369  -  []  271.16 243.67 90 top
NOREF#1370  -  []  547.04 222.35 90 top
NOREF#1371  -  []  451.25 186.2 0 top
NOREF#1372  -  []  463.95 249.7 0 top
NOREF#1373  -  []  305.48 175.27 0 top
NOREF#1374  -  []  270.13 268.11 90 top
NOREF#1375  -  []  271.47 189.88 90 top
NOREF#1376  -  []  111.42 192.22 0 top
NOREF#1377  -  []  331.64 242.3 90 top
NOREF#1378  -  []  235.44 194.76 90 top
NOREF#1379  -  []  461 219.95 0 top
NOREF#1380  -  []  547.04 238.75 0 top
NOREF#1381  -  []  232.13 189.88 90 top
NOREF#1382  -  []  253.39 183.61 0 top
NOREF#1383  -  []  317.27 207.24 90 top
NOREF#1384  -  []  226.06 148.23 0 top
NOREF#1385  -  []  456.55 196.32 0 top
NOREF#1386  -  []  308.27 245.28 0 top
NOREF#1387  -  []  211.83 230.23 315 top
NOREF#1388  -  []  308.23 238.18 90 top
NOREF#1389  -  []  213.61 242 90 top
NOREF#1390  -  []  310.19 238.82 0 top
NOREF#1391  -  []  213.22 191.59 0 top
NOREF#1392  -  []  348.23 238.18 90 top
NOREF#1393  -  []  109.94 214.75 90 top
NOREF#1394  -  []  291.64 193.86 90 top
NOREF#1395  -  []  332.54 254.86 90 top
NOREF#1396  -  []  363.98 207.75 0 top
NOREF#1397  -  []  268.25 174.12 90 top
NOREF#1398  -  []  96.99 158.1 0 top
NOREF#1399  -  []  307.75 175.77 0 top
NOREF#1400  -  []  269.53 244.02 0 top
NOREF#1401  -  []  351.47 249.88 90 top
NOREF#1402  -  []  212.54 194.86 90 top
NOREF#1403  -  []  237.14 146.64 90 top
NOREF#1404  -  []  83.67 275.75 90 top
NOREF#1405  -  []  345.68 185.93 0 top
NOREF#1406  -  []  263.27 234.62 0 top
NOREF#1407  -  []  307.63 247.23 90 top
NOREF#1408  -  []  267.64 180.73 90 top
NOREF#1409  -  []  331.16 240.15 0 top
NOREF#1410  -  []  307.77 173.98 0 top
NOREF#1411  -  []  285.83 229.63 90 top
NOREF#1412  -  []  455.2 189.85 0 top
NOREF#1413  -  []  272.79 243.4 90 top
NOREF#1414  -  []  270.84 178.82 90 top
NOREF#1415  -  []  255.16 251.22 90 top
NOREF#1416  -  []  283.72 271.73 90 top
NOREF#1417  -  []  117.24 249.7 0 top
NOREF#1418  -  []  264.91 233.9 0 top
NOREF#1419  -  []  230.83 241.42 90 top
NOREF#1420  -  []  367.65 160.09 90 top
NOREF#1421  -  []  355.83 281.88 90 top
NOREF#1422  -  []  351.69 209.1 0 top
NOREF#1423  -  []  220.66 226.14 0 top
NOREF#1424  -  []  349.85 184.32 90 top
NOREF#1425  -  []  268.23 238.18 0 top
NOREF#1426  -  []  226.61 190.18 90 top
NOREF#1427  -  []  263.09 173.82 0 top
NOREF#1428  -  []  355.12 294.17 0 top
NOREF#1429  -  []  232.14 191.08 0 top
NOREF#1430  -  []  253.22 240.02 0 top
NOREF#1431  -  []  95.99 249.7 0 top
NOREF#1432  -  []  232.13 181.42 90 top
NOREF#1433  -  []  39.86 254.33 90 top
NOREF#1434  -  []  312.46 182.37 90 top
NOREF#1435  -  []  231.69 209.1 0 top
NOREF#1436  -  []  352.45 242.37 90 top
NOREF#1437  -  []  229.23 180.41 0 top
NOREF#1438  -  []  211.31 254.76 0 top
NOREF#1439  -  []  339.33 196.13 0 top
NOREF#1440  -  []  220.66 166.14 0 top
NOREF#1441  -  []  467.35 244.1 0 top
NOREF#1442  -  []  355.44 254.76 90 top
NOREF#1443  -  []  304.09 231.46 90 top
NOREF#1444  -  []  243.15 211.05 0 top
NOREF#1445  -  []  456 277.11 90 top
NOREF#1446  -  []  568.79 150.18 0 top
NOREF#1447  -  []  312.2 284.47 0 top
NOREF#1448  -  []  47.19 272.5 90 top
NOREF#1449  -  []  551.12 154.21 90 top
NOREF#1450  -  []  332.66 193.56 90 top
NOREF#1451  -  []  462.75 221.6 0 top
NOREF#1452  -  []  349.33 210.27 0 top
NOREF#1453  -  []  242.57 220.09 0 top
NOREF#1454  -  []  219.33 196.13 0 top
NOREF#1455  -  []  284.38 213.87 0 top
NOREF#1456  -  []  262.86 166.14 0 top
NOREF#1457  -  []  263.09 174.94 0 top
NOREF#1458  -  []  568.42 166.3 0 top
NOREF#1459  -  []  87.69 249.7 0 top
NOREF#1460  -  []  352.13 242.07 0 top
NOREF#1461  -  []  354.82 281.03 0 top
NOREF#1462  -  []  467.9 221.6 0 top
NOREF#1463  -  []  283.24 268.22 90 top
NOREF#1464  -  []  346.92 189.88 90 top
NOREF#1465  -  []  265.96 188.86 90 top
NOREF#1466  -  []  331.83 170.23 315 top
NOREF#1467  -  []  332.01 183.2 0 top
NOREF#1468  -  []  264.52 282.62 0 top
NOREF#1469  -  []  226.61 239.75 90 top
NOREF#1470  -  []  233.36 181.38 90 top
NOREF#1471  -  []  285.83 169.63 90 top
NOREF#1472  -  []  273.49 291.46 90 top
NOREF#1473  -  []  352.78 183.41 90 top
NOREF#1474  -  []  83.8 293.09 0 top
NOREF#1475  -  []  90.88 233.93 90 top
NOREF#1476  -  []  331.34 183.29 0 top
NOREF#1477  -  []  303.95 234.94 90 top
NOREF#1478  -  []  539.65 207.34 90 top
NOREF#1479  -  []  271.16 246.26 90 top
NOREF#1480  -  []  343.92 295.57 0 top
NOREF#1481  -  []  534.61 233.03 0 top
NOREF#1482  -  []  247.4 267.92 90 top
NOREF#1483  -  []  348.27 184.64 90 top
NOREF#1484  -  []  335.56 192.47 90 top
NOREF#1485  -  []  232.14 180.12 0 top
NOREF#1486  -  []  283.72 211.73 0 top
NOREF#1487  -  []  353.63 138.2 0 top
NOREF#1488  -  []  366.75 209.12 0 top
NOREF#1489  -  []  312.13 181.42 90 top
NOREF#1490  -  []  230.5 241.72 90 top
NOREF#1491  -  []  487.64 205.05 0 top
NOREF#1492  -  []  116.29 183 90 top
NOREF#1493  -  []  344.52 290.49 0 top
NOREF#1494  -  []  235.83 283.46 0 top
NOREF#1495  -  []  308.93 180.74 90 top
NOREF#1496  -  []  265.43 295.26 0 top
NOREF#1497  -  []  230.84 247.15 0 top
NOREF#1498  -  []  221.29 292.89 0 top
NOREF#1499  -  []  323.37 213.06 90 top
NOREF#1500  -  []  250.33 222.13 90 top
NOREF#1501  -  []  313.99 208.8 90 top
NOREF#1502  -  []  37.86 248.1 0 top
NOREF#1503  -  []  228.44 262.36 0 top
NOREF#1504  -  []  326.03 274.19 0 top
NOREF#1505  -  []  361.44 250.47 0 top
NOREF#1506  -  []  327.65 220.09 90 top
NOREF#1507  -  []  464.85 278.68 0 top
NOREF#1508  -  []  212.33 253.86 90 top
NOREF#1509  -  []  468.1 217.95 0 top
NOREF#1510  -  []  477.18 223.97 0 top
NOREF#1511  -  []  253.09 243.29 90 top
NOREF#1512  -  []  232.23 167.99 90 top
NOREF#1513  -  []  272.79 243.4 0 top
NOREF#1514  -  []  211.64 183.61 0 top
NOREF#1515  -  []  303.71 285.98 90 top
NOREF#1516  -  []  306.6 250.18 90 top
NOREF#1517  -  []  213.09 194.86 90 top
NOREF#1518  -  []  212.43 15.11 0 top
NOREF#1519  -  []  268.01 173.3 90 top
NOREF#1520  -  []  320.04 137.42 90 top
NOREF#1521  -  []  356.22 282.25 90 top
NOREF#1522  -  []  267.58 243.28 0 top
NOREF#1523  -  []  547.04 235.3 90 top
NOREF#1524  -  []  349.89 246.26 0 top
NOREF#1525  -  []  252.78 239.12 90 top
NOREF#1526  -  []  347.05 133.3 0 top
NOREF#1527  -  []  240.81 208.22 90 top
NOREF#1528  -  []  311.16 179.12 90 top
NOREF#1529  -  []  245.29 272.67 0 top
NOREF#1530  -  []  474.25 189.85 0 top
NOREF#1531  -  []  482.51 229.07 90 top
NOREF#1532  -  []  350.18 183.37 0 top
NOREF#1533  -  []  213.61 193.56 90 top
NOREF#1534  -  []  95.99 186.2 0 top
NOREF#1535  -  []  82.01 274.46 90 top
NOREF#1536  -  []  84.1 291.32 0 top
NOREF#1537  -  []  231.81 239.12 90 top
NOREF#1538  -  []  313.63 143.53 0 top
NOREF#1539  -  []  535.51 232.71 90 top
NOREF#1540  -  []  345.95 188.86 0 top
NOREF#1541  -  []  321.13 207.92 90 top
NOREF#1542  -  []  560.92 295.46 90 top
NOREF#1543  -  []  117.24 154.45 0 top
NOREF#1544  -  []  212.45 238.82 0 top
NOREF#1545  -  []  268.27 245.93 0 top
NOREF#1546  -  []  480.05 188.2 0 top
NOREF#1547  -  []  275.21 281.4 90 top
NOREF#1548  -  []  270.84 247.15 0 top
NOREF#1549  -  []  212.78 190.69 90 top
NOREF#1550  -  []  82.32 276.22 90 top
NOREF#1551  -  []  267.63 247.23 90 top
NOREF#1552  -  []  352.13 182.07 0 top
NOREF#1553  -  []  503.64 226.92 0 top
NOREF#1554  -  []  241.04 135.78 0 top
NOREF#1555  -  []  332.45 190.39 0 top
NOREF#1556  -  []  353.63 140.86 0 top
NOREF#1557  -  []  255.71 253.56 90 top
NOREF#1558  -  []  291.64 195.18 0 top
NOREF#1559  -  []  228.93 180.74 90 top
NOREF#1560  -  []  215.56 180.9 90 top
NOREF#1561  -  []  467.35 180.6 0 top
NOREF#1562  -  []  315.05 250.18 90 top
NOREF#1563  -  []  474.97 2.28 90 top
NOREF#1564  -  []  213.09 243.29 90 top
NOREF#1565  -  []  235.91 163.58 0 top
NOREF#1566  -  []  343.09 174.38 0 top
NOREF#1567  -  []  340.66 226.14 0 top
NOREF#1568  -  []  106.74 154.45 0 top
NOREF#1569  -  []  547.04 238.1 90 top
NOREF#1570  -  []  292.96 254.76 0 top
NOREF#1571  -  []  351.48 181.42 90 top
NOREF#1572  -  []  214.36 194.76 0 top
NOREF#1573  -  []  481.8 189.85 0 top
NOREF#1574  -  []  230.57 268.63 0 top
NOREF#1575  -  []  334.68 195.18 0 top
NOREF#1576  -  []  267.85 138.1 0 top
NOREF#1577  -  []  293.66 183.2 0 top
NOREF#1578  -  []  212.66 193.56 90 top
NOREF#1579  -  []  311.11 292.69 90 top
NOREF#1580  -  []  333.99 182.3 90 top
NOREF#1581  -  []  233.76 183.65 0 top
NOREF#1582  -  []  231.54 244.64 0 top
NOREF#1583  -  []  271.48 241.42 90 top
NOREF#1584  -  []  212.96 183.2 0 top
NOREF#1585  -  []  254.31 193.56 90 top
NOREF#1586  -  []  264.09 171.46 0 top
NOREF#1587  -  []  349.89 245.61 0 top
NOREF#1588  -  []  253.66 194.76 0 top
NOREF#1589  -  []  450.05 221.6 0 top
NOREF#1590  -  []  273.11 250.18 90 top
NOREF#1591  -  []  325.58 273.87 90 top
NOREF#1592  -  []  231.19 183 0 top
NOREF#1593  -  []  263.27 173.14 0 top
NOREF#1594  -  []  455.67 276.81 0 top
NOREF#1595  -  []  58.01 254.72 0 top
NOREF#1596  -  []  215.06 243.2 0 top
NOREF#1597  -  []  223.95 234.94 90 top
NOREF#1598  -  []  467.84 233.61 90 top
NOREF#1599  -  []  480.6 253.35 0 top
NOREF#1600  -  []  315.12 295.18 0 top
NOREF#1601  -  []  212.01 254.76 0 top
NOREF#1602  -  []  350.18 182.62 0 top
NOREF#1603  -  []  335.16 239.65 90 top
NOREF#1604  -  []  236.23 163.88 90 top
NOREF#1605  -  []  279.72 136.37 0 top
NOREF#1606  -  []  358.83 268.22 0 top
NOREF#1607  -  []  353.99 268.8 90 top
NOREF#1608  -  []  42.06 297.73 90 top
NOREF#1609  -  []  303.95 172.9 90 top
NOREF#1610  -  []  363.98 267.75 90 top
NOREF#1611  -  []  278.32 141.41 90 top
NOREF#1612  -  []  252.54 183.29 90 top
NOREF#1613  -  []  238.22 208.86 0 top
NOREF#1614  -  []  308.22 182.08 90 top
NOREF#1615  -  []  339.41 226.69 0 top
NOREF#1616  -  []  123.19 255.27 90 top
NOREF#1617  -  []  37.68 268.47 0 top
NOREF#1618  -  []  353.34 270 0 top
NOREF#1619  -  []  268.93 180.09 90 top
NOREF#1620  -  []  211.34 194.86 0 top
NOREF#1621  -  []  109.42 228.97 0 top
NOREF#1622  -  []  332.78 179.12 90 top
NOREF#1623  -  []  294.38 254.86 0 top
NOREF#1624  -  []  360.81 218.16 90 top
NOREF#1625  -  []  245.9 272.03 0 top
NOREF#1626  -  []  268.66 166.14 0 top
NOREF#1627  -  []  224.96 135.33 0 top
NOREF#1628  -  []  540.03 220.67 90 top
NOREF#1629  -  []  566.42 154.6 0 top
NOREF#1630  -  []  361.34 136.1 0 top
NOREF#1631  -  []  286.24 296.96 90 top
NOREF#1632  -  []  307.94 241.05 0 top
NOREF#1633  -  []  211.83 263.63 0 top
NOREF#1634  -  []  268.23 238.18 90 top
NOREF#1635  -  []  102.08 170.11 90 top
NOREF#1636  -  []  265.43 292.08 90 top
NOREF#1637  -  []  351.15 241.72 90 top
NOREF#1638  -  []  112.42 200.32 90 top
NOREF#1639  -  []  242.74 269.49 0 top
NOREF#1640  -  []  267.94 241.7 0 top
NOREF#1641  -  []  90.89 214.75 90 top
NOREF#1642  -  []  251.34 243.29 0 top
NOREF#1643  -  []  333.99 242.3 90 top
NOREF#1644  -  []  342.56 286.27 0 top
NOREF#1645  -  []  321.04 135.78 0 top
NOREF#1646  -  []  309.89 186.26 0 top
NOREF#1647  -  []  312.14 180.12 90 top
NOREF#1648  -  []  451.25 249.7 0 top
NOREF#1649  -  []  364.79 211.56 0 top
NOREF#1650  -  []  267.93 187.56 0 top
NOREF#1651  -  []  307.58 244.06 90 top
NOREF#1652  -  []  466.15 186.2 0 top
NOREF#1653  -  []  313.17 291.16 90 top
NOREF#1654  -  []  331.96 242 90 top
NOREF#1655  -  []  546.66 198.36 0 top
NOREF#1656  -  []  232.06 245.29 90 top
NOREF#1657  -  []  311.08 209.73 0 top
NOREF#1658  -  []  275.23 163.88 90 top
NOREF#1659  -  []  88.89 244.1 0 top
NOREF#1660  -  []  211.16 247.72 90 top
NOREF#1661  -  []  348.01 174.3 90 top
NOREF#1662  -  []  270.86 245.29 0 top
NOREF#1663  -  []  334.36 181.55 0 top
NOREF#1664  -  []  313.35 181.38 90 top
NOREF#1665  -  []  357.27 267.24 90 top
NOREF#1666  -  []  364.68 214.19 0 top
NOREF#1667  -  []  103.59 183 90 top
NOREF#1668  -  []  213.66 194.76 0 top
NOREF#1669  -  []  347.41 134.7 0 top
NOREF#1670  -  []  83.8 292.44 90 top
NOREF#1671  -  []  347.25 238.48 90 top
NOREF#1672  -  []  311.44 180.08 90 top
NOREF#1673  -  []  263.09 234.94 0 top
NOREF#1674  -  []  343.95 174.38 90 top
NOREF#1675  -  []  503.94 223.69 0 top
NOREF#1676  -  []  212.66 242 90 top
NOREF#1677  -  []  499.83 206.03 90 top
NOREF#1678  -  []  102.38 138.68 0 top
NOREF#1679  -  []  334.66 241.23 0 top
NOREF#1680  -  []  252.33 193.86 90 top
NOREF#1681  -  []  294.36 243.2 0 top
NOREF#1682  -  []  299.42 293.48 0 top
NOREF#1683  -  []  237.27 207.24 90 top
NOREF#1684  -  []  263.09 232.9 0 top
NOREF#1685  -  []  467.84 141.55 0 top
NOREF#1686  -  []  252.54 254.86 90 top
NOREF#1687  -  []  269.59 245.93 0 top
NOREF#1688  -  []  114.84 158.1 0 top
NOREF#1689  -  []  232.45 183.7 90 top
NOREF#1690  -  []  549.55 170.72 0 top
NOREF#1691  -  []  63.57 254.33 0 top
NOREF#1692  -  []  313.34 270 0 top
NOREF#1693  -  []  295.83 259.63 0 top
NOREF#1694  -  []  233.11 243.7 90 top
NOREF#1695  -  []  37.31 268.08 90 top
NOREF#1696  -  []  352.45 183.7 90 top
NOREF#1697  -  []  347.58 244.06 90 top
NOREF#1698  -  []  226.74 294.64 0 top
NOREF#1699  -  []  283.83 218.13 90 top
NOREF#1700  -  []  360.81 158.16 0 top
NOREF#1701  -  []  238.33 208.22 90 top
NOREF#1702  -  []  90.79 228.07 0 top
NOREF#1703  -  []  345.95 248.85 0 top
NOREF#1704  -  []  293.1 190.39 90 top
NOREF#1705  -  []  332.78 190.69 90 top
NOREF#1706  -  []  349.53 184.02 0 top
NOREF#1707  -  []  331.96 182 90 top
NOREF#1708  -  []  254.01 417.57 90 top
NOREF#1709  -  []  311.54 246.58 0 top
NOREF#1710  -  []  59.94 196.2 0 top
NOREF#1711  -  []  273.34 210 0 top
NOREF#1712  -  []  80 262.93 90 top
NOREF#1713  -  []  350.54 180.4 0 top
NOREF#1714  -  []  351.8 179.12 90 top
NOREF#1715  -  []  456.65 214.75 90 top
NOREF#1716  -  []  272.06 185.29 90 top
NOREF#1717  -  []  102.08 236.15 90 top
NOREF#1718  -  []  245.4 212.03 90 top
NOREF#1719  -  []  485.2 249.7 0 top
NOREF#1720  -  []  228.01 174.3 90 top
NOREF#1721  -  []  102.08 234.26 0 top
NOREF#1722  -  []  332.66 253.56 90 top
NOREF#1723  -  []  356.11 174.13 90 top
NOREF#1724  -  []  232.13 183.41 0 top
NOREF#1725  -  []  365.73 274.51 0 top
NOREF#1726  -  []  219.87 207.91 0 top
NOREF#1727  -  []  265.44 146.16 90 top
NOREF#1728  -  []  272.45 243.7 90 top
NOREF#1729  -  []  102.08 233.61 90 top
NOREF#1730  -  []  271.48 245.96 90 top
NOREF#1731  -  []  274.44 138.77 0 top
NOREF#1732  -  []  330.56 252.32 0 top
NOREF#1733  -  []  487.64 234.26 0 top
NOREF#1734  -  []  312.14 182.07 0 top
NOREF#1735  -  []  263.09 172.9 0 top
NOREF#1736  -  []  323.54 207.24 90 top
NOREF#1737  -  []  109.42 165.47 90 top
NOREF#1738  -  []  352.78 189.88 90 top
NOREF#1739  -  []  345.95 188.86 0 top
NOREF#1740  -  []  255.06 183.2 0 top
NOREF#1741  -  []  223.95 233.82 90 top
NOREF#1742  -  []  322.34 207.24 0 top
NOREF#1743  -  []  272.16 241.38 0 top
NOREF#1744  -  []  305.33 134.7 0 top
NOREF#1745  -  []  343.95 234.94 90 top
NOREF#1746  -  []  271.54 246.58 0 top
NOREF#1747  -  []  263.71 288.65 90 top
NOREF#1748  -  []  320.81 158.16 90 top
NOREF#1749  -  []  240.48 209.12 0 top
NOREF#1750  -  []  311.48 185.96 90 top
NOREF#1751  -  []  81.69 274.76 90 top
NOREF#1752  -  []  461 244.1 0 top
NOREF#1753  -  []  362.33 173.13 90 top
NOREF#1754  -  []  95.31 197.47 90 top
NOREF#1755  -  []  315.21 281.4 90 top
NOREF#1756  -  []  364.6 208.22 90 top
NOREF#1757  -  []  282.56 209.25 90 top
NOREF#1758  -  []  111.42 128.72 0 top
NOREF#1759  -  []  350.24 185.28 0 top
NOREF#1760  -  []  273.03 294.95 0 top
NOREF#1761  -  []  101.59 212.35 0 top
NOREF#1762  -  []  358.32 141.41 90 top
NOREF#1763  -  []  313.34 210 0 top
NOREF#1764  -  []  325.73 213.87 90 top
NOREF#1765  -  []  214.66 181.23 0 top
NOREF#1766  -  []  478.18 168.57 90 top
NOREF#1767  -  []  283.54 207.24 90 top
NOREF#1768  -  []  265.88 235.27 0 top
NOREF#1769  -  []  345.06 166.14 0 top
NOREF#1770  -  []  212.45 190.39 0 top
NOREF#1771  -  []  128.92 417.57 90 top
NOREF#1772  -  []  309.25 134 0 top
NOREF#1773  -  []  352.23 230.19 90 top
NOREF#1774  -  []  225.48 235.27 0 top
NOREF#1775  -  []  292.33 253.86 90 top
NOREF#1776  -  []  501.19 223.2 0 top
NOREF#1777  -  []  350.91 187.24 90 top
NOREF#1778  -  []  348.44 262.36 0 top
NOREF#1779  -  []  257.83 271.13 0 top
NOREF#1780  -  []  362.57 220.09 0 top
NOREF#1781  -  []  244.35 271.05 90 top
NOREF#1782  -  []  304.42 235.77 0 top
NOREF#1783  -  []  332.78 250.69 90 top
NOREF#1784  -  []  346.94 204.26 0 top
